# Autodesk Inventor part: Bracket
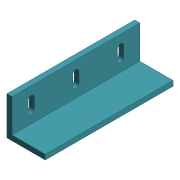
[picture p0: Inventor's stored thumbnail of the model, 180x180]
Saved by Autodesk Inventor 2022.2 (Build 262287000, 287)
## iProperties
Created: 2021-08
Part Number: Bracket
Material: アルミニウム 6061
Document SubType Name: Modeling
Designer: taeku
Density: 2.7 g/cm^3
Appearance: くすんだ青
Author: taeku
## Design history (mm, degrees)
sketch "スケッチ1"
  geometry: L1 (0, 0)-(30, 0); L2 (30, 0)-(30, 4); L3 (30, 4)-(4, 4); L4 (4, 4)-(4, 30); L5 (4, 30)-(0, 30); L6 (0, 30)-(0, 0)
  constraints: 12 end point, 5 perpendicular, 1 horizontal, 1 vertical
  dimensions: "幅" = 30 distance of L1.start L1.end; "d1" = 30 distance of L5.end L1.start (= 幅); "厚み" = 4 distance of L1.end L2.end
extrude "押し出し1" new body sketch "スケッチ1" taper "d4" = 0 deg
sketch "スケッチ2"
  geometry: L1 (15, 17)-(15, 9); L2 (12.5, 17)-(12.5, 9); L3 (17.5, 9)-(17.5, 17); L4 (0, 0)-(0, 26) reference; A1 r 2.5 centre (15, 17) between (17.5, 17) and (12.5, 17); A2 r 2.5 centre (15, 9) between (12.5, 9) and (17.5, 9); 3 further points
  constraints: 8 end point, 4 point on circle, 4 tangent, 2 centre point, 2 midpoint, 1 horizontal alignment, 1 parallel, 1 vertical
  dimensions: "端からの距離" = 15 distance between parallel lines of L1 L4; "d6" = 8 distance of L1.start L1.end; "d7" = 5 distance between parallel lines of L3 L2
extrude "押し出し2" cut sketch "スケッチ2" extent not by distance; stored distance "d8" = 0; taper "d9" = 0 deg
pattern_linear "矩形状パターン1" dims "d12" = 35 (derived)
node "ソリッド1"
